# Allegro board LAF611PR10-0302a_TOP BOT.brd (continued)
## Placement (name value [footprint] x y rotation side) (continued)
PD7  S SCH DIO 5A 100V 15UA 0.88V TO227-3  [PDS5100H-13_POWERDI5-3]  41.3 111.3 90 bottom
PD10  -  [LRB715FT1G_SOT323-3]  35.34 120.07 180 bottom
PD12  -  [DFLS160-7_POWERDI123-2]  44.68 128.93 0 bottom
PD13  AZ4024-02S_SOT23  [PJSOT24C_SOT23-3]  252.73 27.76 270 top
PD14  AZ4024-02S_SOT23  [PJSOT24C_SOT23-3]  229.26 51.54 180 top
PD501  RB751V-40_SOD323-2  [SDMK0340L-7-F_SOD323-2]  132.49 59.04 180 bottom
PDB01  RB751V-40_SOD323-2  [SDMK0340L-7-F_SOD323-2]  274.7 50.69 90 top
PDB02  RB751V-40_SOD323-2  [SDMK0340L-7-F_SOD323-2]  272.82 47.12 270 top
PDB03  RB751V-40_SOD323-2  [SDMK0340L-7-F_SOD323-2]  274.52 47.12 270 top
PDB04  -  [BAT54CW_SOT323-3]  35.46 40.08 90 top
PDB05  RB751V-40_SOD323-2  [SDMK0340L-7-F_SOD323-2]  32.85 33.98 180 top
PDS01  -  [BAT54CW_SOT323-3]  36.28 123.19 270 top
PDS02  S SCH DIO 5A 100V 15UA 0.88V TO227-3  [PDS5100H-13_POWERDI5-3]  28.88 48.35 90 bottom
PDS03  -  [LRB715FT1G_SOT323-3]  27.33 38.56 0 bottom
PDS04  RB751V-40_SOD323-2  [SDMK0340L-7-F_SOD323-2]  30.89 43.44 270 bottom
PDS05  RB751V-40_SOD323-2  [SDMK0340L-7-F_SOD323-2]  27.41 43.46 270 bottom
PDS06  RB751V-40_SOD323-2  [SDMK0340L-7-F_SOD323-2]  29.15 43.45 270 bottom
PDS07  S SCH DIO 5A 100V 15UA 0.88V TO227-3  [PDS5100H-13_POWERDI5-3]  23.86 48.35 90 bottom
PHV01  220K_0402_5%_B25/50 4700K  [R_0402]  218.72 73.28 90 bottom
PHZ01  220K_0402_5%_ERTJ0EV224J  [R_0402]  89.85 131.39 180 bottom
PHZ02  220K_0402_5%_ERTJ0EV224J  [R_0402]  51.6 138.99 90 bottom
PHZ03  220K_0402_5%_ERTJ0EV224J  [R_0402]  87.15 141.48 90 bottom
PHZ04  220K_0402_5%_ERTJ0EV224J  [R_0402]  54.25 147.01 90 bottom
PHZ05  100K_0402_1%_TSM0B104F4251RZ  [R_0402]  95.91 130.68 0 bottom
PJP1  -  [JUMP_43X118]  44.89 134.64 270 top
PJP3  -  [JUMP_43X79]  217.54 43.92 180 bottom
PJP4  -  [JUMP_43X118]  50.18 134.63 270 top
PJP301  -  [JUMP_43X39]  214.81 55.57 180 top
PJP302  -  [JUMP_43X118]  199.47 52.14 180 bottom
PJP303  -  [JUMP_43X118]  199.47 52.14 180 top
PJP501  -  [JUMP_43X79]  121.39 54.18 0 top
PJP502  -  [JUMP_43X118]  127.79 49.1 180 top
PJP503  -  [JUMP_43X118]  127.28 43.89 180 top
PJP901  -  [JUMP_43X39]  48.35 110.03 90 bottom
PJP902  -  [JUMP_43X118]  53.7 112.51 270 bottom
PJP1001  -  [JUMP_43X39]  203.61 70.86 90 top
PJP1002  -  [JUMP_43X79]  199.8 83.05 270 bottom
PJP1801  -  [JUMP_43X39]  196.49 66.24 90 top
PJP1802  -  [JUMP_43X79]  205.6 63.13 270 top
PJP2501  -  [JUMP_43X39]  127.15 59.89 90 bottom
PJP2502  -  [JUMP_43X39]  117.83 61.89 180 top
PJPB01  -  [JUMP_43X118]  240.77 31.37 90 top
PJPB02  -  [JUMP_43X118]  224.69 40.65 90 top
PJPB03  -  [JUMP_43X118]  219.41 40.71 90 top
PJPB04  -  [JUMP_43X118]  229.8 45.44 180 top
PJPB05  -  [JUMP_43X118]  229.8 44.67 180 bottom
PJPB06  -  [JUMP_43X118]  234.63 53.72 0 top
PJPB07  -  [JUMP_43X118]  221.05 44.7 180 bottom
PJPB08  -  [JUMP_43X118]  246.05 31.37 90 top
PJPDC1  ACES_51202-00901-001  [ACES_51202-00901-001_9P-T]  35.71 138.45 0 bottom
PJPH01  -  [JUMP_43X39]  141.99 56.66 180 bottom
PJPH02  -  [JUMP_43X118]  149.67 55.17 0 bottom
PJPH03  -  [JUMP_43X118]  150.76 48.84 0 bottom
PJPM01  -  [JUMP_43X39]  40.3 47.12 180 top
PJPM02  -  [JUMP_43X118]  40.27 67.7 0 top
PJPM03  -  [JUMP_43X39]  41.22 42.39 270 top
PJPM04  -  [JUMP_43X118]  40.27 62.46 0 top
PJPW01  -  [JUMP_43X39]  266.92 74.29 180 top
PJPW02  -  [JUMP_43X118]  264.92 88.38 90 top
PJPW03  -  [JUMP_43X118]  259.59 88.38 90 top
PL1  5A_Z120_25M_0805_2P  [5A_Z120_0805_2P]  44.72 134.72 270 bottom
PL3  BLM15AG102SN1D_2P  [MURAT_BLM15AG102SN1D_2P]  39.57 141.18 0 top
PL4  5A_Z120_25M_0805_2P  [5A_Z120_0805_2P]  217.81 39.19 180 bottom
PL5  5A_Z120_25M_0805_2P  [5A_Z120_0805_2P]  46.5 134.73 270 bottom
PL6  5A_Z120_25M_0805_2P  [5A_Z120_0805_2P]  48.3 134.73 270 bottom
PL7  5A_Z120_25M_0805_2P  [5A_Z120_0805_2P]  217.81 41.05 180 bottom
PL301  1.5UH_9A_20%_7X7X3_M  [L_7X7X3_M_2P]  204.73 52.92 270 bottom
PL311  5A_Z120_25M_0805_2P  [5A_Z120_0805_2P]  214.99 55.24 180 bottom
PL501  1.5UH_9A_20%_7X7X3_M  [L_7X7X3_M_2P]  122.33 48.46 0 bottom
PL511  5A_Z120_25M_0805_2P  [5A_Z120_0805_2P]  119.86 54.49 0 bottom
PL901  1UH_PCMB042T-1R0MS_4.5A_20%  [CYNTE_PCMB042T-1R0MS_2P]  52.52 118.5 270 bottom
PL911  5A_Z120_25M_0805_2P  [5A_Z120_0805_2P]  46.33 110.03 90 bottom
PL1001  1UH_6.6A_20%_5X5X3_M  [MAGLA_MMD-05CZ-1R0M-M7L_2P]  204.33 80.26 90 bottom
PL1011  5A_Z120_25M_0805_2P  [5A_Z120_0805_2P]  200.34 72.82 0 bottom
PL1801  1UH_6.6A_20%_5X5X3_M  [L_5X5X3_M_2P]  205.91 68 270 bottom
PL1811  5A_Z120_25M_0805_2P  [5A_Z120_0805_2P]  195.03 68.62 0 bottom
PLA01  0.47UH_MMD05CZR47M_12A_20%  [MAG_MMD05CZR47M_4P]  97.99 137.83 270 bottom
PLB01  2.2UH_TMPA1005S-2R2MN-D_17.5A_20%  [TAI-T_TMPA1005S-2R2MN-D_2P]  243.17 44.7 180 bottom
PLB11  5A_Z120_25M_0805_2P  [5A_Z120_0805_2P]  217.04 34.82 90 top
PLB12  5A_Z120_25M_0805_2P  [5A_Z120_0805_2P]  218.86 34.81 90 top
PLB13  5A_Z120_25M_0805_2P  [5A_Z120_0805_2P]  220.68 34.82 90 top
PLG01  0.15UH_MMD-06CZER15MEX5L__35A_20%  [L_7X7X3_M]  53.91 140.66 0 bottom
PLH01  1UH_11A_20%_7X7X3_M  [L_7X7X3_M_2P]  141.49 49.99 0 bottom
PLH11  5A_Z120_25M_0805_2P  [5A_Z120_0805_2P]  142.54 54.63 180 bottom
PLI01  0.15UH_MMD-06CZER15MEX5L__35A_20%  [L_7X7X3_M]  92.99 135.53 180 bottom
PLI02  0.15UH_MMD-06CZER15MEX5L__35A_20%  [L_7X7X3_M]  81.07 143.41 270 bottom
PLI03  0.15UH_MMD-06CZER15MEX5L__35A_20%  [L_7X7X3_M]  73.49 143.41 270 bottom
PLI04  0.15UH_MMD-06CZER15MEX5L__35A_20%  [L_7X7X3_M]  65.79 143.41 270 bottom
PLI11  FBMA-L11-453215800LMA90T_2P  [KC_FBMA-L11-453215800LMA90T_2P]  115.91 111.29 180 bottom
PLIV11  FBMA-L11-453215800LMA90T_2P  [KC_FBMA-L11-453215800LMA90T_2P]  217.97 54.08 90 bottom
PLM01  1UH_11A_20%_7X7X3_M  [L_7X7X3_M_2P]  37.26 59.44 270 bottom
PLM11  5A_Z120_25M_0805_2P  [5A_Z120_0805_2P]  41.85 47.41 180 bottom
PLS11  5A_Z120_25M_0805_2P  [5A_Z120_0805_2P]  23.95 62.52 270 top
PLS12  5A_Z120_25M_0805_2P  [5A_Z120_0805_2P]  22.12 62.52 270 top
PLV01  0.22UH_MMD-06DZER22MEM2L__32A_20%  [L_7X7X4_M]  213.62 73.45 90 bottom
PLV02  0.22UH_MMD-06DZER22MEM2L__32A_20%  [L_7X7X4_M]  224.37 73.62 90 bottom
PLV03  0.22UH_MMD-06DZER22MEM2L__32A_20%  [L_7X7X4_M]  235.08 73.41 90 bottom
PLW01  0.82UH_MMD-06CZ-R82M-V1L_13A_20%  [MAG_MMD-06CZ-R82M-V1L_2P]  260.67 82.04 180 bottom
PLW11  5A_Z120_25M_0805_2P  [5A_Z120_0805_2P]  268.22 74.38 180 bottom
PQ1  -  [FDV301N-G_SOT23-3]  42.88 138.4 0 top
PQ2  -  [LMBT3904WT1G_SC70-3]  48.69 142.99 90 top
PQ3  -  [AON7409_DFN8-5]  37.11 116.57 180 top
PQ4  -  [AON7409_DFN8-5]  35.13 108.9 0 top
PQ5  -  [2N7002KW_SOT323-3]  35.91 117.38 270 bottom
PQ6  -  [2N7002KW_SOT323-3]  31.22 109.68 90 bottom
PQ7  -  [AON7409_DFN8-5]  42.19 116.64 180 top
PQ8  -  [AON7409_DFN8-5]  40.22 108.98 0 top
PQ11  -  [2N7002KW_SOT323-3]  274.62 60.44 180 top
PQ12  -  [2N7002KDW_SOT363-6]  45.65 126.32 0 bottom
PQ13  -  [2N7002KDW_SOT363-6]  53.96 140.75 180 top
PQ15  -  [2N7002KW_SOT323-3]  31.27 112.94 270 top
PQ16  -  [2N7002KW_SOT323-3]  32.57 116.63 180 top
PQ17  -  [2N7002KW_SOT323-3]  27.94 112.94 90 bottom
PQ18  -  [2N7002KW_SOT323-3]  32.53 113.63 0 bottom
PQ19  -  [AO3409_SOT23-3]  45.19 111.38 180 top
PQ20  -  [2N7002KW_SOT323-3]  44.26 125.55 270 bottom
PQ21  -  [2N7002KW_SOT323-3]  30.49 116.04 90 top
PQB01  -  [AON6962_DFN5X6D-8-7]  250.58 36.93 180 bottom
PQB02  -  [AON6962_DFN5X6D-8-7]  234.5 51.12 90 bottom
PQB03  -  [AON7409_DFN8-5]  222.44 41.12 270 bottom
PQB04  -  [2N7002KW_SOT323-3]  273.56 55.52 270 top
PQB05  -  [2N7002KW_SOT323-3]  269.19 60.22 270 top
PQB06  -  [AON7380_DFN3X3-8-5]  228.58 50.28 270 bottom
PQB07  -  [AON6962_DFN5X6D-8-7]  246.7 51.58 0 bottom
PQB10  -  [LTC015EUBFS8TL_UMT3F]  267.75 43.12 270 top
PQB11  -  [LMUN5113T1G_SOT323-3]  266.27 39.3 0 top
PQH01  -  [AON6962_DFN5X6D-8-7]  135 53.44 0 bottom
PQM01  -  [AONH36334_DFN3X3A8-10]  38.3 50.06 270 bottom
PQS01  -  [AON7409_DFN8-5]  23.81 53.87 180 top
PQS02  -  [AON7409_DFN8-5]  21.84 46.17 0 top
PQS03  -  [2N7002KW_SOT323-3]  31.12 48.9 180 top
PQS04  -  [2N7002KW_SOT323-3]  33.72 51.38 270 bottom
PQS05  -  [2N7002KDW_SOT363-6]  21.59 42.85 270 top
PQS06  -  [AO3409_SOT23-3]  22.96 41.88 270 bottom
PQS07  2N7002KW_SOT323-3  [DMN65D8LW-7_SOT323-3]  24.99 40.96 180 bottom
PQS08  -  [2N7002KW_SOT323-3]  32.77 48.5 0 bottom
PQS10  -  [2N7002KDW_SOT363-6]  22.65 115.68 180 top
PQS11  -  [2N7002KW_SOT323-3]  18.57 113.01 180 top
PQS12  -  [2N7002KW_SOT323-3]  32.27 55.71 0 bottom
PQS13  -  [AO3409_SOT23-3]  24.44 55.19 270 bottom
PQS15  -  [AON7409_DFN8-5]  28.32 53.93 180 top
PQS16  -  [AON7409_DFN8-5]  26.33 46.2 0 top
PQS17  -  [AON7409_DFN8-5]  26.34 55.82 0 top
PQS18  -  [AON7409_DFN8-5]  21.83 55.86 0 top
PQS19  -  [2N7002KW_SOT323-3]  29.83 56.95 270 top
PQS20  -  [AO3409_SOT23-3]  34.44 53.87 0 top
PQS21  2N7002KW_SOT323-3  [DMN65D8LW-7_SOT323-3]  35.9 59.64 270 top
PQS22  -  [2N7002KDW_SOT363-6]  67.56 42.67 180 top
PQW01  AON6962 2N DFN5X6D  [AON6962_DFN5X6D-8-7]  263.2 77.56 270 bottom
PR1  33_0402_5%  [R_0402]  48.07 138.8 0 top
PR2  0_0402_5%  [R_0402]  33.57 118.96 270 top
PR3  100K_0402_1%  [R_0402]  44.86 142.15 90 top
PR4  10K_0402_1%  [R_0402]  46.1 140.4 90 top
PR5  2.2K_0402_5%  [R_0402]  48.98 137.95 180 top
PR6  15K_0402_1%  [R_0402]  45.66 143.06 270 top
PR7  100K_0402_1%  [R_0402]  45.28 141.31 270 top
PR8  1M_0402_5%  [R_0402]  41.19 117.93 180 top
PR9  1M_0402_5%  [R_0402]  41.41 107.64 0 top
PR10  1M_0402_5%  [R_0402]  35.33 117.85 90 top
PR11  510K_0402_5%  [R_0402]  30.84 110.49 0 top
PR12  1M_0402_5%  [R_0402]  37.54 106.08 0 top
PR13  100K_0402_5%  [R_0402]  34.71 118.97 180 bottom
PR14  10K_0402_5%  [R_0402]  36.39 123.93 270 bottom
PR15  12K_0402_1%  [R_0402]  34.8 123.02 90 bottom
PR16  100K_0402_5%  [R_0402]  35.59 123.02 90 bottom
PR17  56K_0402_5%  [R_0402]  31.76 109.69 270 top
PR22  100K_0402_5%  [R_0402]  32.07 115.7 270 bottom
PR31  0_0402_5%  [R_0402]  54.15 142.62 180 top
PR32  3.3K_1206_5%  [R_1206]  51.01 138.22 90 top
PR33  10K_0402_1%  [R_0402]  46.43 122.67 180 bottom
PR34  1M_0402_1%  [R_0402]  53.01 137.28 0 top
PR35  0_0402_5%  [R_0402]  53.2 144.29 270 top
PR36  1M_0402_1%  [R_0402]  48.03 127.4 180 bottom
PR37  100_0402_5%  [R_0402]  209.74 35.94 90 top
PR38  1M_0402_1%  [R_0402]  53.93 138.07 180 top
PR39  200_0402_5%  [R_0402]  211.39 35.94 90 top
PR40  100K_0402_1%  [R_0402]  47.93 124.07 90 bottom
PR41  10K_0402_1%  [R_0402]  210.56 36.85 270 top
PR42  100_0402_5%  [R_0402]  207.98 39.23 0 top
PR43  100K_0402_1%  [R_0402]  274.14 57.52 0 top
PR44  1M_0402_1%  [R_0402]  45.46 127.39 0 bottom
PR45  1M_0402_1%  [R_0402]  53.23 141.82 0 top
PR46  0_0402_5%  [R_0402]  32.49 111.37 0 top
PR47  300K_0402_5%  [R_0402]  34.97 106.7 180 top
PR48  100K_0402_5%  [R_0402]  33.27 106.7 180 top
PR50  100K_0402_5%  [R_0402]  30.91 114.61 270 bottom
PR51  0_0402_5%  [R_0402]  32.54 109.72 0 top
PR52  0_0402_5%  [R_0402]  32.49 110.56 0 top
PR62  100K_0402_5%  [R_0402]  36.93 118.67 90 bottom
PR63  15K_0402_5%  [R_0402]  36.93 120.37 90 bottom
PR64  100K_0402_1%  [R_0402]  43.71 122.68 90 bottom
PR65  0_0402_5%  [R_0402]  28.85 103 0 top
PR100  1M_0402_5%  [R_0402]  33.02 117.35 180 bottom
PR301  0_0603_5%  [R_0603]  210.08 52.93 90 bottom
PR302  499K_0402_1%  [R_0402]  127.71 57.83 90 bottom
PR303  150K_0402_1%  [R_0402]  128.53 57.83 90 bottom
PR304  10K_0402_1%  [R_0402]  214.1 48.04 90 bottom
PR305  4.7_1206_5%  [R_1206]  205.88 54.15 180 top
PR306  1K_0402_5%  [R_0402]  210.36 45.33 90 bottom
PR307  150K_0402_1%  [R_0402]  210.31 46.99 0 bottom
PR308  150K_0402_1%  [R_0402]  212.03 47.02 270 bottom
PR501  0_0603_5%  [R_0603]  121.13 52.88 180 bottom
PR502  0_0402_5%  [R_0402]  212.9 47.02 270 bottom
PR503  0_0402_5%  [R_0402]  128.61 55.75 90 bottom
PR504  10K_0402_1%  [R_0402]  126.94 58.48 270 bottom
PR505  4.7_1206_5%  [R_1206]  122.29 49.68 270 top
PR506  2.2K_0402_5%  [R_0402]  130.48 57.8 180 bottom
PR507  0_0402_5%  [R_0402]  131.8 57.69 0 bottom
PR508  1M_0402_5%  [R_0402]  129.45 55.89 0 bottom
PR509  1K_0402_5%  [R_0402]  129.52 53.29 180 bottom
PR510  150K_0402_1%  [R_0402]  128.61 54.11 90 bottom
PR511  150K_0402_1%  [R_0402]  129.5 55.06 0 bottom
PR901  10K_0402_5%  [R_0402]  43.2 119.74 270 bottom
PR902  0_0603_5%  [R_0603]  48.79 113.88 270 bottom
PR903  0_0402_5%  [R_0402]  44.06 119.06 0 bottom
PR904  1M_0402_1%  [R_0402]  45.7 120.03 90 bottom
PR905  0_0402_5%  [R_0402]  45.85 119.91 0 top
PR906  0_0402_5%  [R_0402]  46.52 120.94 270 bottom
PR907  4.7_1206_5%  [R_1206]  51.46 120.6 0 bottom
PR908  10_0402_1%  [R_0402]  49.07 121.75 180 bottom
PR909  21K_0402_1%  [R_0402]  48.17 120.94 270 bottom
PR910  35.7K_0402_1%  [R_0402]  47.35 120.03 90 bottom
PR911  0_0402_5%  [R_0402]  48.11 122.96 0 bottom
PR912  0_0402_5%  [R_0402]  47.35 121.74 90 bottom
PR913  0_0402_5%  [R_0402]  44.87 120.94 270 bottom
PR1001  6.81K_0402_1%  [R_0402]  207.12 74.32 0 bottom
PR1002  10K_0402_5%  [R_0402]  206.22 77.34 180 top
PR1003  4.7_0603_5%  [R_0603]  202.52 77.9 180 bottom
PR1004  10K_0402_1%  [R_0402]  207.11 73.45 0 bottom
PR1005  0_0402_5%  [R_0402]  207.73 79.13 270 bottom
PR1006  0_0402_5%  [R_0402]  206.93 79.13 270 bottom
PR1007  1M_0402_1%  [R_0402]  206.89 77.41 270 bottom
PR1801  0_0402_5%  [R_0402]  199.9 64.71 0 bottom
PR1802  1M_0402_5%  [R_0402]  201.64 65.59 270 bottom
PR1803  100K_0402_5%  [R_0402]  202.4 64.68 90 bottom
PR1804  4.7_1206_5%  [R_1206]  202.91 70.81 0 bottom
PR1805  10K_0402_1%  [R_0402]  198.16 65.57 0 bottom
PR1806  0_0402_5%  [R_0402]  198.17 63.92 0 bottom
PR1807  20K_0402_1%  [R_0402]  196.32 65.99 0 bottom
PR2501  0_0402_5%  [R_0402]  124.93 67.32 0 bottom
PR2502  21.5K_0402_1%  [R_0402]  117.31 64.58 90 bottom
PR2503  10K_0402_1%  [R_0402]  117.43 66.27 0 bottom
PR2504  2.2_0402_1%  [R_0402]  123.93 61.09 0 bottom
PRA01  2_0603_5%  [R_0603]  107.91 138.6 270 bottom
PRA02  3.9_0603_1%  [R_0603]  107.74 134.94 0 bottom
PRA04  1_1206_5%  [R_1206]  100.98 138.15 270 top
PRB01  0.005_1206_1%  [R_1206_4P-D]  216.56 32.96 0 top
PRB02  2.2_0402_1%  [R_0402]  268.06 47.41 90 top
PRB03  2.2_0402_1%  [R_0402]  266.24 47.37 90 top
PRB04  0_0402_5%  [R_0402]  270.46 45.12 0 top
PRB05  442K_0402_1%  [R_0402]  271.37 45.99 180 top
PRB06  3.3_0603_1%  [R_0603]  264.63 49.2 270 top
PRB07  100K_0402_5%  [R_0402]  270.46 46.81 0 top
PRB08  1_0805_5%  [R_0805]  272.82 48.8 90 top
PRB09  4.7_0402_5%  [R_0402]  261.48 49.25 270 top
PRB10  95.3K_0402_1%  [R_0402]  272.44 51.69 0 top
PRB11  499K_0402_1%  [R_0402]  273.17 57.47 270 top
PRB12  0.01_1206_1%  [R_1206_4P-D]  231.69 40.97 180 bottom
PRB13  200K_0402_1%  [R_0402]  271.35 52.49 0 top
PRB14  0_0402_5%  [R_0402]  272.26 53.28 180 top
PRB15  4.7_0603_1%  [R_0603]  259.58 50.76 0 top
PRB16  0_0402_5%  [R_0402]  272.26 54.12 180 top
PRB17  4.7_1206_5%  [R_1206]  242.78 47.09 270 top
PRB18  4.7_1206_5%  [R_1206]  238.34 52.98 90 top
PRB19  0_0402_5%  [R_0402]  272.25 54.93 180 top
PRB20  768K_0402_1%  [R_0402]  272.26 56.52 180 top
PRB21  0_0402_5%  [R_0402]  261.57 53 180 top
PRB22  0_0402_5%  [R_0402]  271.33 55.72 0 top
PRB23  1M_0402_1%  [R_0402]  276.44 55.38 0 top
PRB24  100K_0402_1%  [R_0402]  267.17 61.06 180 top
PRB25  100K_0402_1%  [R_0402]  267.97 61.17 270 top
PRB26  316K_0402_1%  [R_0402]  268.31 57.46 90 top
PRB27  100K_0402_1%  [R_0402]  269.92 58.36 270 top
PRB28  0_0402_5%  [R_0402]  265.59 57.41 90 top
PRB29  100K_0402_1%  [R_0402]  269.12 58.36 270 top
PRB30  499_0402_1%  [R_0402]  267.46 57.47 90 top
PRB31  0_0402_5%  [R_0402]  264.77 57.41 90 top
PRB32  1_0402_1%  [R_0402]  261.04 54.73 180 top
PRB33  10.5K_0402_1%  [R_0402]  263.97 57.41 90 top
PRB34  0_0402_5%  [R_0402]  263.1 60.83 180 top
PRB35  0_0402_5%  [R_0402]  263.1 61.64 180 top
PRB36  1_0402_1%  [R_0402]  261.04 55.65 180 top
PRB37  0_0402_5%  [R_0402]  38.75 39.12 0 top
PRB38  0_0402_5%  [R_0402]  39.66 39.93 180 top
PRB39  100_0402_5%  [R_0402]  262.19 59.14 0 top
PRB40  0_0402_5%  [R_0402]  37.69 38.43 180 top
PRB41  0_0402_5%  [R_0402]  34.44 35.05 90 top
PRB42  0_0402_5%  [R_0402]  39.28 34.85 180 top
PRB43  1M_0402_1%  [R_0402]  276.44 56.17 0 top
PRB44  0_0402_5%  [R_0402]  28.27 33.98 0 top
PRB45  1M_0402_1%  [R_0402]  277.35 56.98 180 top
PRB46  0_0603_5%  [R_0603]  238.42 50.56 0 top
PRB50  100K_0402_5%  [R_0402]  260.71 44.86 0 top
PRB51  47K_0402_1%  [R_0402]  269.25 46 180 top
PRB57  0_0402_5%  [R_0402]  252.67 55.57 0 top
PRB59  0_0402_5%  [R_0402]  262.19 59.99 0 top
PRB60  200K_0402_1%  [R_0402]  271.66 57.55 180 top
PRB61  0_0402_5%  [R_0402]  235.38 45.72 0 top
PRB65  0_0603_5%  [R_0603]  264.38 41.64 270 top
PRB66  0_0603_5%  [R_0603]  263.13 40.25 90 top
PRB67  0_0603_5%  [R_0603]  281.39 54.82 90 top
PRB68  100_0402_5%  [R_0402]  262.19 57.4 0 top
PRB69  0_0603_5%  [R_0603]  282.66 54.82 90 top
PRB70  374K_0402_1%  [R_0402]  269.58 44.28 180 top
PRG01  2_0603_5%  [R_0603]  55.61 151.55 0 bottom
PRG02  3.9_0603_1%  [R_0603]  59.37 151.38 90 bottom
PRG03  10_0402_1%  [R_0402]  58.38 139.73 270 top
PRG04  1_1206_5%  [R_1206]  55.57 144.3 0 top
PRH01  100K_0402_1%  [R_0402]  137.71 37.89 90 bottom
PRH02  2.2_0603_5%  [R_0603]  138.46 43 90 bottom
PRH03  22.1K_0402_1%  [R_0402]  136.93 37.89 90 bottom
PRH04  0_0402_5%  [R_0402]  72.19 47.92 180 top
PRH05  470K_0402_1%  [R_0402]  132.19 38.64 90 bottom
PRH06  4.7_1206_5%  [R_1206]  140.34 45.54 270 bottom
PRH10  4.99K_0402_1%  [R_0402]  133.31 38.84 270 bottom
PRH13  10K_0402_1%  [R_0402]  134.13 38.83 270 bottom
PRH14  10K_0402_1%  [R_0402]  137.74 38.47 180 top
PRI01  2_0603_5%  [R_0603]  88.24 146.28 0 bottom
PRI02  3.9_0603_1%  [R_0603]  90.75 146.23 0 bottom
PRI03  10_0402_1%  [R_0402]  88.49 137.12 90 top
PRI04  1_1206_5%  [R_1206]  88.77 139.41 0 top
PRI05  2_0603_5%  [R_0603]  80.38 152.33 0 bottom
PRI06  3.9_0603_1%  [R_0603]  84.14 152.15 90 bottom
PRI07  10_0402_1%  [R_0402]  83.44 138.97 90 top
PRI08  1_1206_5%  [R_1206]  80.31 145.42 0 top
PRI09  2_0603_5%  [R_0603]  72.15 152.32 0 bottom
PRI10  3.9_0603_1%  [R_0603]  75.88 152.15 90 bottom
PRI11  10_0402_1%  [R_0402]  75.79 138.91 90 top
PRI12  1_1206_5%  [R_1206]  72.04 145.46 0 top
PRI13  2_0603_5%  [R_0603]  63.87 152.32 0 bottom
PRI14  3.9_0603_1%  [R_0603]  67.63 152.15 90 bottom
PRI15  10_0402_1%  [R_0402]  68.23 138.92 90 top
PRI16  1_1206_5%  [R_1206]  63.84 145.41 0 top
PRM01  4.7_1206_5%  [R_1206]  39.82 52.73 180 top
PRM02  2.2_0603_5%  [R_0603]  37.8 46.62 180 bottom
PRM03  15.4K_0402_1%  [R_0402]  33.84 45.25 180 bottom
PRM04  5.1_0603_5%  [R_0603]  32.43 41.84 0 bottom
PRM05  2.2_0603_5%  [R_0603]  33.82 43.05 180 bottom
PRM06  10K_0402_1%  [R_0402]  35.28 38.75 90 bottom
PRM07  453K_0402_1%  [R_0402]  36.07 38.75 90 bottom
PRM08  0_0402_5%  [R_0402]  37.05 38.75 90 bottom
PRM09  0_0402_5%  [R_0402]  39.71 38.74 90 bottom
PRM10  60.4K_0402_1%  [R_0402]  41.7 39.83 90 bottom
PRM11  100K_0402_1%  [R_0402]  40.77 38.95 0 bottom
PRS01  1.8M_0402_1%  [R_0402]  35.27 125.75 180 top
PRS02  1K_0402_1%  [R_0402]  34.33 124.88 0 top
PRS03  240K_0402_1%  [R_0402]  36.94 125.74 180 top
PRS04  102K_0402_1%  [R_0402]  33.27 128.87 180 top
PRS05  23.2K_0402_1%  [R_0402]  31.31 130.45 180 top
PRS06  84.5K_0402_1%  [R_0402]  32.36 128.1 0 top
PRS07  100K_0402_5%  [R_0402]  20.7 61.01 180 top
PRS08  499K_0402_1%  [R_0402]  20.23 56.2 270 bottom
PRS09  499K_0402_1%  [R_0402]  24.63 44.26 270 bottom
PRS10  300K_0402_1%  [R_0402]  19.06 41.82 270 bottom
PRS11  49.9K_0402_1%  [R_0402]  20.23 54.53 270 bottom
PRS12  100K_0402_5%  [R_0402]  30.67 50.21 0 top
PRS14  1M_0402_5%  [R_0402]  31.59 51.14 90 top
PRS15  100K_0402_5%  [R_0402]  22.89 39.39 270 bottom
PRS16  49.9K_0402_1%  [R_0402]  24.64 42.48 0 bottom
PRS23  0_0402_5%  [R_0402]  29.01 38.81 90 bottom
PRS25  1M_0402_1%  [R_0402]  19.49 41.22 90 top
PRS26  1M_0402_1%  [R_0402]  20.34 116.35 270 top
PRS27  1M_0402_1%  [R_0402]  20.03 113.73 90 top
PRS28  10K_0402_1%  [R_0402]  24.11 111.95 90 top
PRS29  100K_0402_1%  [R_0402]  21.11 112.92 180 top
PRS30  100K_0402_1%  [R_0402]  20.19 110.96 90 top
PRS32  0_0402_5%  [R_0402]  29.9 38.81 90 bottom
PRS33  0_0402_5%  [R_0402]  28.22 39.76 180 bottom
PRS34  10K_0402_1%  [R_0402]  24.82 36.36 90 bottom
PRS36  300K_0402_1%  [R_0402]  30.34 55.26 0 top
PRS37  100K_0402_5%  [R_0402]  32.06 55.27 270 top
PRS38  0_0402_5%  [R_0402]  30.35 54.37 0 top
PRS39  0_0402_5%  [R_0402]  34.36 126.51 0 top
PRS40  0_0402_5%  [R_0402]  29.01 38.05 270 bottom
PRS41  0_0402_5%  [R_0402]  25.64 37.27 270 bottom
PRS42  499K_0402_1%  [R_0402]  27.25 55.86 0 bottom
PRS43  49.9K_0402_1%  [R_0402]  28.89 56.62 90 bottom
PRS44  300K_0402_1%  [R_0402]  33.86 57.86 0 top
PRS45  10K_0402_1%  [R_0402]  31.01 59.84 270 top
PRS46  100K_0402_5%  [R_0402]  35.51 57.86 0 top
PRS47  0_0402_5%  [R_0402]  31.9 59.84 270 top
PRS48  1M_0402_5%  [R_0402]  26.49 41.17 180 top
PRS49  100K_0402_5%  [R_0402]  66.82 40 0 top
PRS50  100K_0402_5%  [R_0402]  66.92 39.03 180 top
PRS51  100K_0402_5%  [R_0402]  68.63 42.15 270 top
PRV01  4.7K_0402_5%  [R_0402]  254.03 64.39 90 top
PRV02  4.7K_0402_5%  [R_0402]  254.79 64.39 90 top
PRV03  0_0402_5%  [R_0402]  254.91 63.75 90 bottom
PRV04  10K_0402_5%  [R_0402]  256.21 63.75 90 bottom
PRV05  2_0603_5%  [R_0603]  255.34 66.6 0 top
PRV06  0_0402_5%  [R_0402]  254.91 65.43 0 bottom
PRV07  100_0402_5%  [R_0402]  255.47 67.64 0 top
PRV08  0_0402_5%  [R_0402]  256.97 64.67 0 bottom
PRV09  0_0402_5%  [R_0402]  256.4 67.78 180 bottom
PRV10  10K_0402_5%  [R_0402]  254.91 62.89 270 top
PRV11  100_0402_5%  [R_0402]  255.47 68.53 0 top
PRV13  0_0402_5%  [R_0402]  254.1 62.89 270 top
PRV14  0_0402_5%  [R_0402]  256.4 68.63 180 bottom
PRV15  6.19K_0402_1%  [R_0402]  255.59 62.95 180 bottom
PRV16  4.32K_0402_1%  [R_0402]  254.79 60.53 270 bottom
PRV17  20.5K_0402_1%  [R_0402]  253.77 61.24 270 bottom
PRV18  309_0402_1%  [R_0402]  255.55 60.53 270 bottom
PRV19  16.5K_0402_1%  [R_0402]  254.71 61.26 0 bottom
PRV20  49.9_0402_1%  [R_0402]  252.25 70.86 90 bottom
PRV21  3.3K_0402_1%  [R_0402]  254.82 71.71 0 bottom
PRV22  1K_0402_0.5%  [R_0402]  253.05 70.82 0 bottom
PRV23  1K_0402_1%  [R_0402]  251.99 61.19 180 top
PRV24  41.2K_0402_1%  [R_0402]  251.31 70.86 90 bottom
PRV25  23.2K_0402_1%  [R_0402]  250.55 70.86 90 bottom
PRV26  24.3K_0402_1%  [R_0402]  248.69 70.86 90 bottom
PRV27  15K_0402_1%  [R_0402]  247.68 71.78 270 bottom
PRV28  75K_0402_1%  [R_0402]  250.34 70.13 270 top
PRV29  10K_0402_5%  [R_0402]  251.1 60.32 90 bottom
PRV30  26.1K_0402_1%  [R_0402]  250.34 60.32 90 bottom
PRV31  37.4K_0402_1%  [R_0402]  249.58 60.32 90 bottom
PRV32  37.4K_0402_1%  [R_0402]  248.82 60.32 90 bottom
PRV33  1K_0402_5%  [R_0402]  248.06 60.32 90 bottom
PRV34  1K_0402_5%  [R_0402]  247.29 60.32 90 bottom
PRV35  1K_0402_5%  [R_0402]  246.53 60.32 90 bottom
PRV36  147K_0402_1%  [R_0402]  247.55 69.21 90 top
PRV37  100K_0402_1%  [R_0402]  244.93 69.98 0 bottom
PRV38  1K_0402_5%  [R_0402]  248.58 63.52 180 top
PRV39  200K_0603_1%  [R_0603]  243.4 69.1 0 top
PRV40  100K_0402_1%  [R_0402]  245.1 68.03 90 bottom
PRV41  200K_0603_1%  [R_0603]  243.41 67.87 0 top
PRV42  200K_0603_1%  [R_0603]  243.4 66.62 0 top
PRV43  100K_0402_1%  [R_0402]  245.94 67.07 270 bottom
PRV44  3.24K_0402_1%  [R_0402]  244.19 66.61 180 bottom
PRV45  3.24K_0402_1%  [R_0402]  244.27 67.93 180 bottom
PRV46  3.24K_0402_1%  [R_0402]  244.28 68.94 180 bottom
PRV47  2_0603_5%  [R_0603]  217.65 63.01 90 bottom
PRV48  3.9_0603_1%  [R_0603]  215.23 64.35 270 bottom
PRV49  4.7_1206_5%  [R_1206]  214.1 71.05 0 top
PRV50  10_0402_1%  [R_0402]  209.1 77.06 90 bottom
PRV51  2_0603_5%  [R_0603]  227.74 62.79 90 bottom
PRV52  3.9_0603_1%  [R_0603]  225.34 64.23 270 bottom
PRV53  4.7_1206_5%  [R_1206]  227.84 71.53 180 top
PRV54  10_0402_1%  [R_0402]  219.81 77.06 90 bottom
PRV55  2_0603_5%  [R_0603]  237.78 62.94 90 bottom
PRV56  3.9_0603_1%  [R_0603]  235.38 64.34 270 bottom
PRV57  4.7_1206_5%  [R_1206]  237.72 71.32 180 top
PRV58  10_0402_1%  [R_0402]  230.57 77.06 90 bottom
PRW01  2.2_0603_5%  [R_0603]  260.01 67.37 0 bottom
PRW02  2.2_0402_1%  [R_0402]  267.83 65.62 0 bottom
PRW03  383K_0402_1%  [R_0402]  268.75 67.41 180 bottom
PRW04  4.7_1206_5%  [R_1206]  263.83 83.2 270 bottom
PRW05  2.2_0603_5%  [R_0603]  260.96 71.7 0 bottom
PRW06  0_0402_1%  [R_0402]  264.48 72.16 270 bottom
PRW07  12.4K_0402_1%  [R_0402]  265.3 72.17 270 bottom
PRW08  10K_0402_1%  [R_0402]  265.07 71.25 90 top
PRW09  100K_0402_1%  [R_0402]  266.13 72.17 270 bottom
PRW10  0_0402_1%  [R_0402]  266.96 72.17 270 bottom
PRW11  5.62K_0402_1%  [R_0402]  268.75 68.22 180 bottom
PRW12  51K_0402_1%  [R_0402]  267.83 69.86 0 bottom
PRW13  3.3K_0402_1%  [R_0402]  267.83 69.04 0 bottom
PRW14  100_0402_5%  [R_0402]  267.82 64.82 0 bottom
PRW15  25.5K_0402_1%  [R_0402]  265.68 68.53 0 top
PRW16  1800P_0402_50V7K  [C_0402]  266.59 69.42 180 top
PRW17  66.5K_0402_1%  [R_0402]  264.32 65.03 270 bottom
PRW18  10K_0402_1%  [R_0402]  263.36 64.13 90 bottom
PRW19  0_0402_1%  [R_0402]  266.43 64.13 90 bottom
PRZ02  0_0402_5%  [R_0402]  103.73 141.33 90 bottom
PRZ03  1.21K_0402_1%  [R_0402]  105.48 141.38 90 top
PRZ05  0_0402_5%  [R_0402]  102.9 140.57 0 bottom
PRZ06  1.58K_0402_1%  [R_0402]  104.59 141.35 90 bottom
PRZ08  0_0402_5%  [R_0402]  101.73 143.31 0 top
PRZ10  0_0402_5%  [R_0402]  100.15 143.33 90 bottom
PRZ11  1.69K_0402_1%  [R_0402]  101.91 144.18 0 bottom
PRZ12  12K_0402_1%  [R_0402]  108.03 141.38 90 top
PRZ13  7.5K_0603_1%  [R_0603]  108.36 139.2 270 top
PRZ14  29.4K_0402_1%  [R_0402]  108.8 144.87 270 top
PRZ15  12.4K_0402_1%  [R_0402]  106.18 143.85 90 top
PRZ16  1.5K_0402_1%  [R_0402]  105.49 141.49 270 bottom
PRZ17  10K_0402_1%  [R_0402]  108.86 141.37 90 top
PRZ18  34.8K_0402_1%  [R_0402]  109.56 143.96 90 top
PRZ19  0_0402_5%  [R_0402]  109.01 142.16 270 bottom
PRZ20  499_0402_1%  [R_0402]  112.15 142.16 270 bottom
PRZ21  100_0402_1%  [R_0402]  111.21 141.37 90 top
PRZ22  45.3_0402_1%  [R_0402]  110.43 142.29 270 top
PRZ23  45.3_0402_1%  [R_0402]  109.64 142.29 270 top
PRZ24  100_0402_1%  [R_0402]  112.83 143.81 0 bottom
PRZ25  49.9_0402_1%  [R_0402]  109.8 142.29 270 bottom
PRZ26  0_0402_5%  [R_0402]  110.58 141.37 90 bottom
PRZ27  10_0402_1%  [R_0402]  111.36 142.29 270 bottom
PRZ28  49.9_0402_1%  [R_0402]  100.15 145.94 270 bottom
PRZ29  3.65K_0402_1%  [R_0402]  101.86 147.76 180 bottom
PRZ30  1K_0402_1%  [R_0402]  101.91 145.07 0 bottom
PRZ31  25.5K_0402_1%  [R_0402]  104.4 146.08 0 top
PRZ32  27.4K_0402_1%  [R_0402]  100.94 148.59 0 bottom
PRZ33  75K_0402_1%  [R_0402]  100.92 146.76 90 top
PRZ34  158K_0402_1%  [R_0402]  101.29 148.52 0 top
PRZ35  115K_0603_1%  [R_0603]  100.98 150.53 0 top
PRZ36  115K_0603_1%  [R_0603]  100.98 151.8 0 top
PRZ37  115K_0603_1%  [R_0603]  100.98 153.07 0 top
PRZ38  115K_0603_1%  [R_0603]  100.98 154.34 0 top
PRZ40  0_0402_5%  [R_0402]  112.77 144.67 0 top
PRZ41  1.37K_0402_1%  [R_0402]  112.83 145.56 0 bottom
PRZ42  0_0402_5%  [R_0402]  114.58 145.55 270 bottom
PRZ44  31.6K_0402_1%  [R_0402]  110.44 146.07 180 top
PRZ45  49.9_0402_1%  [R_0402]  113.63 146.4 0 bottom
PRZ46  1K_0402_1%  [R_0402]  112.82 147.28 270 bottom
PRZ47  3.65K_0402_1%  [R_0402]  113.68 146.42 0 top
PRZ48  12.1K_0402_1%  [R_0402]  113.58 148.16 0 top
PRZ49  75K_0402_1%  [R_0402]  114.49 149.03 90 top
PRZ50  165K_0402_1%  [R_0402]  113.65 149.95 180 top
PRZ51  88.7K_0603_1%  [R_0603]  113.05 150.11 0 bottom
PRZ52  1K_0402_1%  [R_0402]  105.32 153.31 270 top
PRZ53  2.2_0603_5%  [R_0603]  106.42 153.96 270 top
PRZ54  100K_0402_1%  [R_0402]  106.99 151.09 270 top
PRZ55  4.32K_0402_1%  [R_0402]  107.38 153.27 90 bottom
PRZ56  24.9K_0402_1%  [R_0402]  107.77 151.28 270 top
PRZ57  97.6K_0402_1%  [R_0402]  108.17 153.27 90 bottom
PRZ58  24.9K_0402_1%  [R_0402]  109.33 150.96 270 top
PRZ59  25.5K_0402_1%  [R_0402]  108.97 153.27 90 bottom
PRZ60  1.62K_0402_1%  [R_0402]  113.53 150.78 0 top
PRZ61  1.62K_0402_1%  [R_0402]  100.95 150.12 0 bottom
PRZ62  1.62K_0402_1%  [R_0402]  100.95 151.65 0 bottom
PRZ63  1.62K_0402_1%  [R_0402]  100.95 153.17 0 bottom
PRZ64  1.62K_0402_1%  [R_0402]  100.95 154.69 0 bottom
PRZ66  0_0402_5%  [R_0402]  104.49 152.43 180 top
PRZ67  61.9K_0402_1%  [R_0402]  103.49 152.38 90 bottom
PRZ68  0_0402_5%  [R_0402]  110.72 152.63 90 bottom
PRZ69  61.9K_0402_1%  [R_0402]  110.7 152.75 180 top
PRZ70  10_0402_1%  [R_0402]  107.19 141.38 90 top
PRZ71  1K_0402_1%  [R_0402]  113.8 151.19 180 bottom
PRZ72  97.6K_0402_1%  [R_0402]  108.54 150.96 270 top
PRZ73  100K_0402_1%  [R_0402]  100.95 149.36 0 bottom
PRZ74  100K_0402_1%  [R_0402]  100.95 150.88 0 bottom
PRZ75  100K_0402_1%  [R_0402]  100.95 152.41 0 bottom
PRZ76  100K_0402_1%  [R_0402]  100.95 153.93 0 bottom
PRZ77  1K_0402_1%  [R_0402]  112.57 151.76 180 top
PU01  -  [RT9069-33GB_SOT23-5]  40.82 120.79 270 bottom
PU301  -  [SY8288BRAC_QFN20_3X3]  210.34 51.61 270 bottom
PU501  SY8180CRAC_QFN20_3X3  [SY8288CRAC_QFN20_3X3]  123.88 53.87 0 bottom
PU901  -  [SY8286RAC_QFN20_3X3]  48.75 115.49 90 bottom
PU1001  -  [RT8061AZQW_WDFN10_3X3]  203.81 77.7 0 bottom
PU1801  -  [RT8061AZQW_WDFN10_3X3]  201.87 68.74 270 bottom
PU2501  -  [RT9059GSP_SO8]  125.01 66.13 270 bottom
PUA01  NCP302035MNTXG_PQFN33_5X5  [NCP302045MNTXG_PQFN33_5X5]  106.4 137.95 270 bottom
PUB01  -  [ISL9538HRTZ-T_TQFN32_4X4]  264.83 54.88 0 top
PUB02  -  [TC7SH08FU_SSOP5]  35.41 36.72 270 top
PUG01  -  [NCP302045MNTXG_PQFN33_5X5]  56.37 150.05 0 bottom
PUH01  -  [TPS51212DSCR_SON10_3X3]  136.35 40.06 180 bottom
PUI01  -  [NCP302045MNTXG_PQFN33_5X5]  89.53 144.79 0 bottom
PUI02  -  [NCP302045MNTXG_PQFN33_5X5]  81.13 150.81 0 bottom
PUI03  -  [NCP302045MNTXG_PQFN33_5X5]  72.88 150.81 0 bottom
PUI04  -  [NCP302045MNTXG_PQFN33_5X5]  64.62 150.81 0 bottom
PUM01  -  [RT8207PGQW_WQFN20_3X3]  38.9 43.62 270 bottom
PUS01  -  [LM393DGKR_VSSOP8]  33.01 126.71 270 top
PUS02  -  [TC7SH08FU_SSOP5]  21.87 38.95 90 top
PUS03  -  [TC7SH32FU_SSOP5]  25.31 38.95 90 top
PUS04  RT9058-33GX SOT-89 3P  [AP2204R-5P0TRG1_SOT89-3]  35.44 69.22 0 bottom
PUV01  -  [NCP302045MNTXG_PQFN33_5X5]  217.78 65.84 180 bottom
PUV02  -  [NCP302045MNTXG_PQFN33_5X5]  227.66 66.04 180 bottom
PUV03  -  [NCP302045MNTXG_PQFN33_5X5]  237.74 65.92 180 bottom
PUV101  -  [NCP81276MNTXG_QFN40_5X5]  252.18 63.29 90 bottom
PUW01  -  [RT8816AGQW_WQFN20_3X3]  263.74 69.52 0 bottom
PUZ01  -  [NCP81215MNTXG_QFN52_6X6]  104.81 145.18 0 bottom
Q1  -  [2N7002K_SOT23-3]  166.15 27.7 0 bottom
Q6  -  [LN2306LT1G_SOT23-3]  32.03 74.5 180 bottom
Q7  -  [DDTA144VCA-7-F_SOT23-3]  31.93 69.8 180 bottom
Q8  DMN65D8LW-7_SOT323-3  [SSM3K7002FU_SC70-3]  155.27 45.35 180 bottom
Q9  -  [LN2306LT1G_SOT23-3]  230.66 37.36 90 bottom
Q10  -  [DMN66D0LDW-7_SOT363-6]  226.04 35.27 90 bottom
Q11  -  [DMN66D0LDW-7_SOT363-6]  199.74 58.1 180 top
Q12  NTK3139PT1G_SOT723-3  [2N7002K_SOT23-3]  234.24 37.21 0 top
Q13  -  [2N7002K_SOT23-3]  241.66 37.82 90 top
Q14  -  [LMBT3904LT1G_SOT23-3]  114.1 137.47 180 top
Q17  -  [DMN66D0LDW-7_SOT363-6]  29.55 110.2 270 bottom
Q18  -  [DDTA144VCA-7-F_SOT23-3]  24.26 102.31 0 bottom
Q19  -  [DDTA144VCA-7-F_SOT23-3]  8.38 107.42 270 bottom
Q22  -  [LN2306LT1G_SOT23-3]  170.9 27.68 0 bottom
Q23  L2N7002LT1G_SOT23-3  [2N7002K_SOT23-3]  130.33 64.36 0 bottom
Q24  L2N7002LT1G_SOT23-3  [2N7002K_SOT23-3]  272.52 64.27 270 bottom
Q25  -  [L2N7002WT1G_SC-70-3]  173.29 25.61 270 top
Q26  -  [LP2301ALT1G_SOT23-3]  191.24 32.46 0 bottom
Q27  -  [DMN66D0LDW-7_SOT363-6]  163.54 25.8 180 bottom
Q29  -  [L2N7002WT1G_SC-70-3]  30.25 79.64 0 bottom
Q30  -  [L2N7002WT1G_SC-70-3]  23.13 120.98 90 top
QA1  -  [LN2306LT1G_SOT23-3]  38.06 25.63 180 top
QG10  L2N7002WT1G_SC-70-3  [2N7002W-T-R7_SOT323-3]  212.87 87.62 270 bottom
QG23  DMN63D8LDW-7 2N SOT363-6  [DMN65D8LDW-7_SOT363-6]  202.14 89.75 270 bottom
QG502  DMN53D0LDW-7 2N SOT363-6  [2N7002DW-7-F_SOT363-6]  241.73 87.14 180 bottom
QG503  DMN53D0LDW-7_SOT363-6  [2N7002DW-7-F_SOT363-6]  195.7 117.75 0 bottom
QG504  DMN53D0LDW-7_SOT363-6  [2N7002DW-7-F_SOT363-6]  192.61 117.76 0 bottom
QG505  DMN53D0LDW-7 2N SOT363-6  [2N7002DW-7-F_SOT363-6]  202.48 92.13 180 bottom
QG506  DMN53D0LDW-7_SOT363-6  [2N7002DW-7-F_SOT363-6]  245.65 85.12 180 bottom
QH4  -  [DMN65D8LDW-7_SOT363-6]  190.69 47.74 315 bottom
QH7  L2N7002LT1G_SOT23-3  [2N7002K_SOT23-3]  174.82 27.05 180 bottom
QH8  -  [L2N7002DW1T1G_SC88-6]  23.55 112.32 180 bottom
QH9  -  [L2N7002DW1T1G_SC88-6]  24.86 103.65 90 top
QH10  DMN53D0LDW-7_SOT363-6  [2N7002DW-7-F_SOT363-6]  194.07 61.1 90 bottom
QS1  -  [DMN66D0LDW-7_SOT363-6]  273.44 39.9 0 top
QV1  DMN53D0LDW-7 2N SOT363-6  [2N7002DW-7-F_SOT363-6]  219.68 88.8 0 bottom
QV3  BSS138W 1N SOT-323-3  [2N7002W-T-R7_SOT323-3]  235.68 87.92 180 bottom
QV10  S TR PJT138KA 2N SOT363-6  [BSS138DW_SC88-6]  224.82 88.19 270 bottom
QV20  BSS138W 1N SOT-323-3  [2N7002W-T-R7_SOT323-3]  240.78 142.37 0 bottom
QV21  BSS138W 1N SOT-323-3  [2N7002W-T-R7_SOT323-3]  255.59 92.02 90 top
QV96  DMN61D9UDW-7 2N SOT363-6  [DMN65D8LDW-7_SOT363-6]  13.87 105.1 0 top
QX3  -  [MMBT3904WH_SOT323-3]  17.81 101.87 0 bottom
R1  1K_0402_5%  [R_0402]  168.54 26.74 90 bottom
R2  10M_0402_5%  [R_0402]  168.54 25.98 270 bottom
R3  0_0805_5%  [R0805_0OHM]  257.96 53.38 270 top
R5  10K_0402_5%  [R_0402]  255.88 50.8 90 top
R6  0_0402_5%  [R0402_0OHM]  255.91 52.48 180 top
R8  0_0402_5%  [R0402_0OHM]  251.43 41.78 0 top
R9  0_0402_5%  [R_0402]  251.43 42.58 0 top
R10  100K_0402_5%  [R_0402]  254.93 47.84 90 top
R13  0_0603_5%  [R_0603]  253.66 35.76 0 top
R16  0_0603_1%  [R0603_0OHM]  259.7 44.4 180 top
R19  33_0402_5%  [R_0402]  253.47 37.29 180 top
R20  0_0402_5%  [R_0402]  260.04 41.69 90 top
R21  0_0402_5%  [R_0402]  259.15 41.69 90 top
R22  100_0402_5%  [R_0402]  273.57 32.84 180 top
R24  100K_0402_5%  [R_0402]  31.01 78.31 0 bottom
R25  1K_0402_5%  [R_0402]  31.52 68.15 0 bottom
R26  51K_0402_5%  [R_0402]  151.64 45.74 270 bottom
R27  100K_0402_5%  [R_0402]  152.4 45.74 270 bottom
R28  18.7K_0402_1%  [R_0402]  203.81 56.87 180 bottom
R29  2K_0402_1%  [R_0402]  195.73 58.64 0 bottom
R30  10K_0402_5%  [R_0402]  254 33.81 0 top
R31  4.7K_0402_5%  [R_0402]  233.12 35.36 270 top
R32  4.7K_0402_5%  [R_0402]  233.88 35.36 270 top
R33  2.2K_0402_5%  [R_0402]  226.44 37.52 0 bottom
R34  2.2K_0402_5%  [R_0402]  191.62 50.24 180 bottom
R35  0_0402_5%  [R0402_0OHM]  237.54 39.84 180 top
R36  0_0603_5%  [R_0603]  237.81 34.97 180 top
R37  100_0603_5%  [R_0603]  237.81 36.24 180 top
R38  20K_0402_1%  [R_0402]  237.59 39.03 270 top
R39  10K_0402_5%  [R_0402]  234.49 36.68 270 bottom
R40  4.7K_0402_5%  [R_0402]  224.29 35.62 180 bottom
R41  100K_0402_5%  [R_0402]  235.31 36.68 270 bottom
R42  7.15K_0402_1%  [R_0402]  64.97 112.6 0 top
R43  7.5K_0402_1%  [R_0402]  64.97 111.83 0 top
R45  0_0402_5%  [R_0402]  104.09 46.02 90 top
R46  2.2K_0402_5%  [R_0402]  229.12 35.09 90 bottom
R47  2.2K_0402_5%  [R_0402]  225.16 35.57 90 bottom
R48  2.2K_0402_5%  [R_0402]  201.06 56.89 90 top
R49  2.2K_0402_5%  [R_0402]  199.36 55.27 180 top
R57  10K_0402_5%  [R_0402]  260.5 48.56 90 top
R68  200_0402_5%  [R_0402]  22.73 104.39 270 bottom
R69  200_0402_5%  [R_0402]  10.06 106.59 90 bottom
R73  10K_0402_5%  [R_0402]  174.45 26.44 270 top
R77  0_0402_5%  [R0402_0OHM]  39.74 30.28 0 top
R78  1M_0402_5%  [R_0402]  169.29 26.62 180 top
R79  100K_0402_5%  [R_0402]  166.04 27.55 0 top
R82  100K_0402_5%  [R_0402]  163.74 28.62 180 bottom
R83  100K_0402_5%  [R_0402]  166.98 28.46 180 top
R3004  0_0201_5%  [R_0201]  31.25 95.63 180 bottom
R3005  0_0201_5%  [R_0201]  31.25 96.27 180 bottom
R3006  0_0201_5%  [R_0201]  34.42 95.7 90 bottom
R3007  0_0201_5%  [R_0201]  35.05 95.7 90 bottom
R3008  0_0201_5%  [R_0201]  35.71 95.85 90 bottom
R3010  0_0201_5%  [R_0201]  36.34 95.85 90 bottom
R3019  0_0201_5%  [R_0201]  42.88 96.23 90 bottom
R3021  0_0201_5%  [R_0201]  43.51 96.23 90 bottom
R3023  0_0201_5%  [R_0201]  44.4 96.23 90 bottom
R3024  0_0201_5%  [R_0201]  45.03 96.23 90 bottom
R3025  0_0201_5%  [R_0201]  45.93 96.21 90 bottom
R3026  0_0201_5%  [R_0201]  46.57 96.21 90 bottom
RA1  0_0805_5%  [R0805_0OHM]  35.65 7.9 180 top
RA2  0_0402_5%  [R0402_0OHM]  38.1 19.1 270 top
RA3  100K_0402_5%  [R_0402]  34.19 20.55 90 top
RA4  0_0603_1%  [R0603_0OHM]  23.14 21.72 270 top
RA5  0_0402_5%  [R0402_0OHM]  38.1 21.85 180 top
RA6  0_0402_5%  [R0402_0OHM]  38.82 21.86 0 top
RA7  33_0402_5%  [R_0402]  36.96 16.69 180 top
RA8  100K_0402_5%  [R_0402]  34.44 12.47 180 top
RA9  0_0402_5%  [R_0402]  35.99 20.22 270 top
RA10  200K_0402_1%  [R_0402]  21.11 18.06 270 top
RA11  0_0402_5%  [R_0402]  29.93 21.16 90 top
RA12  0_0402_5%  [R0402_0OHM]  29.11 21.16 90 top
RA13  BLM15PD800SN1D_2P  [MURAT_BLM15PD600SN1D_2P]  21.29 4.39 180 top
RA14  BLM15PD800SN1D_2P  [MURAT_BLM15PD600SN1D_2P]  21.29 5.6 180 top
RA15  BLM15PD800SN1D_2P  [MURAT_BLM15PD600SN1D_2P]  24.55 6.14 270 top
RA16  BLM15PD800SN1D_2P  [MURAT_BLM15PD600SN1D_2P]  25.78 3.23 180 top
RA17  0_0402_5%  [R0402_0OHM]  32.28 22.55 90 top
RA18  0_0402_5%  [R0402_0OHM]  24.28 10.74 0 top
RA22  0_0805_5%  [R0805_0OHM]  21.35 9.68 270 top
RA23  1K_0402_5%  [R_0402]  34.24 23.7 0 top
RA24  10K_0402_5%  [R_0402]  35.15 22.93 180 top
RA25  2.2K_0402_5%  [R_0402]  15.95 13.16 0 top
RA26  2.2K_0402_5%  [R_0402]  18.77 13.16 180 top
RA27  10_0402_1%  [R_0402]  21.79 13.69 180 top
RA28  1K_0402_5%  [R_0402]  23.95 16.08 0 top
RA29  4.7K_0402_5%  [R_0402]  21.79 12.93 180 top
RA30  10K_0402_5%  [R_0402]  15.04 18.07 0 bottom
RA31  10_0402_1%  [R_0402]  21.79 11.4 180 top
RA32  1K_0402_5%  [R_0402]  23.95 15.31 0 top
RA33  4.7K_0402_5%  [R_0402]  21.79 12.17 180 top
RA34  10K_0402_5%  [R_0402]  16.79 18.21 270 bottom
RA40  0_0402_5%  [R0402_0OHM]  19.58 18.06 270 top
RA41  100K_0402_5%  [R_0402]  23.32 19.38 0 top
RA42  33_0402_5%  [R_0402]  37.69 12.9 180 top
RA43  33_0402_5%  [R_0402]  35.97 14.63 180 top
RC1  24.9_0402_1%  [R_0402]  102.45 118.32 180 top
RC2  20_0402_5%  [R_0402]  181.18 58.97 90 bottom
RC3  121_0402_1%  [R_0402]  101.3 94.18 0 top
RC4  75_0402_1%  [R_0402]  101.3 95.71 0 top
RC5  100_0402_1%  [R_0402]  101.3 94.94 0 top
RC6  0_0201_5%  [R_0201]  106.6 125.03 180 bottom
RC7  0_0201_5%  [R_0201]  106.61 125.68 180 bottom
RC8  30_0402_5%  [R_0402]  100.88 115.61 90 top
RC9  24.9_0402_1%  [R_0402]  99.83 112.74 270 top
RC10  100_0402_1%  [R_0402]  85.33 131.11 90 bottom
RC11  100_0402_1%  [R_0402]  84.44 131.11 90 bottom
RC12  100_0402_1%  [R_0402]  81.95 129.38 90 bottom
RC13  100_0402_1%  [R_0402]  82.84 129.38 90 bottom
RC14  0_0805_5%  [R_0805]  99.37 95.38 180 top
RC15  100_0402_1%  [R_0402]  94.95 129.11 0 bottom
RC16  100_0402_1%  [R_0402]  94.21 129.11 180 bottom
RC19  49.9_0402_1%  [R_0402]  58.78 115.52 180 bottom
RC20  1K_0402_5%  [R_0402]  105.82 116.97 90 top
RC22  20_0402_5%  [R_0402]  57.86 120.98 0 bottom
RC44  0_0201_5%  [R_0201]  58.15 122.5 0 bottom
RC45  0_0201_5%  [R_0201]  106.62 123.96 180 bottom
RC46  1K_0402_5%  [R_0402]  107.01 123.24 180 bottom
RC76  51_0402_5%  [R_0402]  58.78 118.57 180 bottom
RC77  51_0402_5%  [R_0402]  58.78 110.92 180 bottom
RC78  51_0402_5%  [R_0402]  58.78 117.8 180 bottom
RC80  1K_0402_5%  [R_0402]  116.93 114.81 270 bottom
RC83  51_0402_5%  [R_0402]  58.78 117.04 180 bottom
RC84  51_0402_5%  [R_0402]  177.97 53.45 0 top
RC85  51_0402_5%  [R_0402]  60.62 119.65 270 top
RC86  1K_0402_5%  [R_0402]  182.26 33.16 180 top
RC144  0_0402_5%  [R_0402]  61.41 119.94 270 top
RC145  0_0402_5%  [R_0402]  179.62 29.98 0 bottom
RC224  10K_0402_5%  [R_0402]  171.48 29.98 0 bottom
RC249  1K_0402_5%  [R_0402]  182.21 29.98 180 bottom
RC250  1K_0402_5%  [R_0402]  63.06 120.31 180 top
RC251  0_0603_5%  [R_0603]  116.93 117.77 270 bottom
RC252  1K_0402_5%  [R_0402]  180.65 35.33 180 top
RC253  1K_0402_5%  [R_0402]  58.79 112.47 180 bottom
RC254  1K_0402_5%  [R_0402]  58.78 113.99 180 bottom
RC255  1K_0402_5%  [R_0402]  58.78 114.76 180 bottom
RC256  1K_0402_5%  [R_0402]  58.78 111.68 180 bottom
RC257  1K_0402_5%  [R_0402]  58.78 113.23 180 bottom
RC258  1K_0402_5%  [R_0402]  58.78 116.28 180 bottom
RC259  51_0402_5%  [R_0402]  57.86 110.13 0 bottom
RC260  100_0402_1%  [R_0402]  69.29 130.17 270 bottom
RC261  56.2_0402_1%  [R_0402]  68.53 130.17 270 bottom
RC262  1K_0402_5%  [R_0402]  55.57 121.22 0 bottom
RC263  49.9_0402_1%  [R_0402]  57.86 124.79 0 bottom
RC264  1K_0402_1%  [R_0402]  179.91 36.9 0 top
RC267  220_0402_5%  [R_0402]  67.77 129.26 180 bottom
RC268  499_0402_1%  [R_0402]  65.2 129.26 0 bottom
RC269  60.4_0402_1%  [R_0402]  97.23 110.55 270 top
RC270  330K_0402_5%  [R_0402]  58.27 106.6 180 bottom
RC271  100_0402_1%  [R_0402]  50.72 108.15 180 bottom
RC272  0_0402_5%  [R_0402]  50.72 108.91 180 bottom
RC273  0_0402_5%  [R_0402]  50.72 109.68 180 bottom
RC274  100_0402_1%  [R_0402]  50.72 110.44 180 bottom
RC275  0_0402_5%  [R_0402]  95.02 129.92 90 bottom
RC276  0_0402_5%  [R_0402]  94.13 129.92 90 bottom
RC277  0_0402_5%  [R_0402]  57.86 121.74 0 bottom
RC442  0_0402_5%  [R_0402]  94.65 25.4 0 top
RD1  0_0402_5%  [R_0402]  110.29 62.71 270 top
RD2  0_0402_5%  [R_0402]  111.2 62.71 270 top
RD3  0_0402_5%  [R_0402]  83.71 57.45 90 top
RD4  0_0402_5%  [R_0402]  109.47 62.32 180 top
RD5  0_0402_5%  [R_0402]  111.21 60.96 180 top
RD6  0_0402_5%  [R_0402]  82.88 58.36 270 top
RD7  470_0402_1%  [R_0402]  84.6 60.27 270 top
RD8  0_0402_5%  [R_0402]  83.78 59.35 90 top
RD9  2_0402_1%  [R_0402]  83.08 63.75 90 top
RD10  1K_0402_1%~D  [R_0402]  84.5 62.15 0 top
RD11  24.9_0402_1%  [R_0402]  81.06 64.53 90 top
RD12  1K_0402_1%~D  [R_0402]  85.45 64.01 90 top
RD13  0_0402_5%  [R_0402]  116.56 48.85 0 top
RD14  0_0402_5%  [R_0402]  119.2 48.85 180 top
RD15  0_0402_5%  [R_0402]  88.72 54.86 0 top
RD16  0_0402_5%  [R_0402]  117.47 49.67 180 top
RD17  0_0402_5%  [R_0402]  118.28 49.68 0 top
RD18  0_0402_5%  [R_0402]  89.63 55.75 180 top
RD19  2_0402_1%  [R_0402]  88.29 52.12 0 top
RD20  1K_0402_1%~D  [R_0402]  92.23 48.16 270 top
RD21  1K_0402_1%~D  [R_0402]  90.51 48.19 0 top
RD22  24.9_0402_1%  [R_0402]  89.64 53.92 180 top
RD23  240_0402_1%  [R_0402]  75.93 61.59 0 top
RD24  240_0402_1%  [R_0402]  79.91 52.77 270 top
RE1  100K_0402_1%  [R_0402]  99.16 36.65 180 top
RE2  0_0603_5%  [R_0603]  70.51 44.17 90 top
RE3  100K_0402_1%  [R_0402]  99.29 34.36 180 top
RE4  100K_0402_1%  [R_0402]  96.22 34.36 0 top
RE6  100K_0402_1%  [R_0402]  96.88 36.4 180 top
RE7  0_0603_5%  [R0603_0OHM]  96.13 40.89 180 top
RE8  4.7K_0402_5%  [R_0402]  87.34 47.31 90 top
RE9  4.7K_0402_5%  [R_0402]  86.56 47.31 90 top
RE10  2.2K_0402_5%  [R_0402]  85.79 47.31 90 top
RE11  2.2K_0402_5%  [R_0402]  85.01 47.31 90 top
RE14  100K_0402_5%  [R_0402]  71.51 43.98 90 top
RE15  100K_0402_5%  [R_0402]  75.68 26.48 180 top
RE16  10K_0402_5%  [R_0402]  77.22 26.57 270 top
RE17  100K_0402_5%  [R_0402]  84.24 47.31 90 top
RE18  100K_0402_5%  [R_0402]  92.23 35.2 270 top
RE19  1K_0402_5%  [R_0402]  82.45 27.08 270 top
RE21  100K_0402_5%  [R_0402]  89.66 48.23 270 top
RE23  43_0402_1%  [R_0402]  90.34 26.78 0 top
RE25  100K_0402_5%  [R_0402]  72.3 25.67 90 top
RE28  0_0402_5%  [R0402_0OHM]  96.55 38.4 0 top
RE29  1K_0402_5%  [R_0402]  98.5 39.83 0 top
RE30  2.2K_0402_5%  [R_0402]  88.55 26.9 270 top
RE31  2.2K_0402_5%  [R_0402]  90.49 25.56 180 top
RE32  100K_0402_5%  [R_0402]  96.29 39.58 0 top
RE37  0_0402_5%  [R0402_0OHM]  102.38 44.22 90 top
RE41  100K_0402_5%  [R_0402]  94.67 46.97 270 top
RE42  0_0402_5%  [R0402_0OHM]  72.09 37.92 0 top
RE43  100_0402_5%  [R_0402]  96.18 46.2 0 top
RE45  0_0402_5%  [R_0402]  92.47 42.61 0 top
RE46  10K_0402_1%  [R_0402]  75.45 48.18 270 top
RE47  0_0402_5%  [R_0402]  92.23 41.74 0 top
RE48  10K_0402_1%  [R_0402]  77.94 47.26 90 top
RE49  100K_0402_5%  [R_0402]  83.97 26.57 270 top
RE50  0_0603_5%  [R_0603]  93.76 37.34 180 top
RE51  300_0402_5%  [R_0402]  95.96 35.63 0 top
RE52  100K_0402_5%  [R_0402]  103.18 44.22 90 top
RE53  100K_0201_5%  [R_0201]  72.31 34.21 270 top
RE54  300_0402_5%  [R_0402]  96.55 37.57 0 top
RE55  10K_0201_5%  [R_0201]  68.35 31.97 270 top
RE56  100K_0201_5%  [R_0201]  70.26 31.99 180 top
RE57  10K_0201_5%  [R_0201]  70.89 31.97 270 top
RE58  10K_0201_5%  [R_0201]  71.59 31.97 270 top
RE59  49.9_0402_1%  [R_0402]  63.04 31.34 0 top
RE60  0_0201_5%  [R_0201]  63.35 32.28 90 top
RE61  0_0201_5%  [R_0201]  64.11 32.28 90 top
RE62  10K_0201_5%  [R_0201]  69.67 31.38 0 top
RE63  0_0201_5%  [R_0201]  67.72 31.41 90 top
RE65  0_0402_5%  [R_0402-NPM]  71.06 39.89 0 bottom
RE66  0_0603_5%  [R0603_0OHM]  68.54 35.52 0 top
RE67  33_0402_5%  [R_0402-NPM]  73.89 38.41 0 bottom
RE68  10K_0402_5%  [R_0402]  74.12 47.29 90 top
RE70  100K_0402_5%  [R_0402]  93.78 46.06 90 top
RE82  10K_0402_5%  [R_0402]  120.65 58.67 180 bottom
RE85  0_0402_5%  [R0402_0OHM]  70.59 38.89 180 top
RE89  0_0402_5%  [R_0402]  92.22 29.09 90 top
RE90  0_0402_5%  [R_0402]  87.52 26.9 270 top
RE100  10K_0402_5%  [R_0402]  128.68 66.06 270 bottom
RE101  10K_0402_5%  [R_0402]  273.3 61.94 90 bottom
RE104  0_0603_1%  [R0603_0OHM]  116.19 67.28 0 bottom
RE105  0_0603_1%  [R0603_0OHM]  272.25 60.69 0 bottom
RE121  10K_0201_5%  [R_0201]  130.44 60.7 180 bottom
RE122  10K_0201_5%  [R_0201]  272.05 66.61 180 bottom
RE149  0_0201_5%  [R_0201]  71.41 46.15 270 top
RE150  100K_0402_5%  [R_0402]  72.68 46.04 0 top
RE151  10K_0402_5%  [R_0402]  277.58 59.97 270 top
RE152  100K_0402_5%  [R_0402]  120.1 61.06 0 bottom
RE153  100K_0402_5%  [R_0402]  278.92 54.77 0 top
RE155  10K_0402_5%  [R_0402]  72.31 44.89 270 top
RE156  100K_0402_5%  [R_0402]  68.94 38.7 180 top
RE157  100K_0402_5%  [R_0402]  74.02 26.59 270 top
RE158  0_0402_5%  [R0402_0OHM]  78.89 26.03 90 top
RE160  0_0201_5%  [R0201_0OHM]  71.97 46.15 270 top
RE161  10K_0402_5%  [R_0402]  96.18 47.04 0 top
RE162  0_0402_5%  [R_0402]  93.09 28.34 180 top
RE163  0_0402_5%  [R_0402]  92.89 25.39 0 top
RE164  100K_0402_5%  [R_0402]  96.83 28.03 180 top
RE165  100K_0402_5%  [R_0402]  94.44 39.58 0 top
RE166  100K_0402_5%  [R_0402]  81.03 47.23 90 top
RE167  10K_0402_1%  [R_0402]  76.28 48.18 270 top
RE168  10K_0402_5%  [R_0402]  76.44 26.55 270 top
RE169  10K_0402_5%  [R_0402]  75.68 25.67 180 top
RF1  0_0201_5%  [R_0201]  245.94 34.9 0 bottom
RG9  10K_0201_5%  [R_0201]  223.99 92.67 270 bottom
RG37  1K_0402_1%  [R_0402]  210.16 96.9 180 top
RG50  100K_0402_5%  [R_0402]  223.44 89.28 0 bottom
RG51  100K_0402_5%  [R_0402]  223.41 89.32 0 top
RG70  10K_0402_5%  [R_0402]  197.02 120.51 90 bottom
RG505  10K_0201_5%  [R_0201]  204.16 86.43 180 bottom
RG506  10K_0201_5%  [R_0201]  239.9 89.87 0 bottom
RG509  10K_0402_5%  [R_0402]  195.45 114.65 0 bottom
RG510  10_0402_1%  [R_0402]  198.1 115.71 90 bottom
RG511  10K_0402_5%  [R_0402]  192.38 113.92 90 bottom
RG512  10_0402_1%  [R_0402]  194.83 118.93 180 bottom
RG513  10K_0402_5%  [R_0402]  245.78 88.9 270 bottom
RG514  51_0402_5%  [R_0402]  244.21 88.9 270 bottom
RG516  10K_0201_5%  [R_0201]  241.68 90.45 270 bottom
RG543  10K_0402_5%  [R_0402]  202.67 95.1 180 bottom
RG544  10_0402_1%  [R_0402]  201.91 91.03 180 bottom
RG546  10K_0402_5%  [R_0402]  199.26 90.84 270 bottom
RG549  100K_0402_5%  [R_0402]  198.91 95.63 270 bottom
RG550  39K_0402_1%  [R_0402]  199.24 88.2 90 bottom
RG551  0_0201_5%  [R_0201]  199.74 118.1 180 bottom
RG553  0_0201_5%  [R_0201]  241.71 86.34 180 bottom
RG554  0_0201_5%  [R_0201]  241.08 90.42 270 bottom
RG557  10K_0402_5%  [R_0402]  242.92 81.8 180 bottom
RG573  100K_0402_5%  [R_0402]  209.79 85.9 180 bottom
RG575  0_0402_5%  [R_0402]  209.82 86.76 90 bottom
RG576  100K_0402_5%  [R_0402]  204.37 88.07 180 bottom
RG580  0_0402_5%  [R_0402]  204.39 87.12 180 bottom
RH1  100K_0402_1%_B25/50 4250K  [R_0402]  66.67 112.6 0 top
RH4  0_0201_5%  [R_0201]  183.5 29.13 0 bottom
RH11  0_0201_5%  [R_0201]  192.58 33.12 90 bottom
RH12  100K_0201_5%  [R_0201]  191.53 36.16 180 bottom
RH13  30_0402_5%  [R_0402]  175.49 58.95 90 bottom
RH14  13_0402_5%  [R_0402]  174.58 58.95 90 bottom
RH16  1K_0402_1%  [R_0402]  191.92 59.89 270 bottom
RH20  60.4_0402_1%  [R_0402]  173.04 59.86 270 bottom
RH23  10K_0201_5%  [R_0201]  180.39 44.69 180 top
RH24  10K_0201_5%  [R_0201]  180.99 44.69 90 top
RH29  10K_0201_5%  [R_0201]  193.03 52.65 0 bottom
RH30  10K_0201_5%  [R_0201]  191.25 52.65 0 bottom
RH33  2.2K_0402_5%  [R_0402]  187.78 54.68 0 top
RH38  30_0402_5%  [R_0402]  180.41 59.89 270 bottom
RH39  30_0402_5%  [R_0402]  179.65 59.89 270 bottom
RH62  1K_0201_5%  [R_0201]  189.8 44.89 180 top
RH63  1K_0201_5%  [R_0201]  189.82 48.45 0 top
RH64  2.2K_0402_5%  [R_0402]  191.62 49.48 180 bottom
RH65  150K_0402_5%  [R_0402]  189.09 40.5 270 bottom
RH66  2.2K_0402_5%  [R_0402]  192.99 49.48 0 bottom
RH69  10K_0201_5%  [R_0201]  177.72 30.11 180 bottom
RH70  10M_0402_5%  [R_0402]  179.57 31.32 180 top
RH71  2.7K_0402_1%  [R_0402]  171.91 59.87 270 bottom
RH72  1M_0402_5%~D  [R_0402]  155.62 50.26 180 bottom
RH73  13_0402_5%  [R_0402]  176.36 58.95 90 bottom
RH74  4.7K_0402_5%  [R_0402]  202.59 38.76 90 bottom
RH75  100K_0402_5%  [R_0402]  208.78 36.84 270 top
RH78  100K_0402_5%  [R_0402]  205.25 39.5 0 top
RH79  620_0402_5%  [R_0402]  173.82 58.95 90 bottom
RH83  20K_0402_5%~D  [R_0402]  188.46 31.56 90 top
RH84  20K_0402_5%~D  [R_0402]  175.46 25.25 0 bottom
RH89  0_1206_5%  [R_1206]  151.61 34.61 180 top
RH90  100K_0201_5%  [R_0201]  181.98 29.36 0 top
RH93  10K_0402_5%  [R_0402]  181.74 50.16 0 top
RH94  10K_0201_5%  [R_0201]  132.94 31.9 90 top
RH103  0_0201_5%  [R_0201]  126.49 35.65 0 top
RH104  15_0402_1%  [R_0402]  190.17 32.26 180 top
RH105  0_0201_5%  [R_0201]  127.56 34.9 0 top
RH109  113_0402_1%  [R_0402]  167.72 58.1 90 bottom
RH128  10K_0201_5%  [R_0201]  191.3 37.59 180 bottom
RH130  2.2K_0402_5%  [R_0402]  181.18 42.24 0 top
RH135  10K_0201_5%  [R_0201]  189.69 36.98 180 bottom
RH143  0_0402_5%  [R_0402]  179.52 41.74 270 top
RH150  0_0402_5%  [R0402_0OHM]  178.69 40.82 90 top
RH162  0_0402_5%  [R0402_0OHM]  165.14 25.26 0 top
RH174  0_0402_5%  [R_0402]  178.24 44.5 180 top
RH179  10K_0201_5%  [R_0201]  189.36 42.4 90 top
RH180  100K_0201_5%  [R_0201]  131.32 31.89 180 top
RH199  100K_0201_5%  [R_0201]  195.47 33.2 180 bottom
RH453  1K_0201_5%  [R_0201]  184.1 28.51 0 bottom
RH455  1K_0201_5%  [R_0201]  206.77 38.71 180 top
RH462  1K_0201_5%  [R_0201]  195.26 49.05 180 bottom
